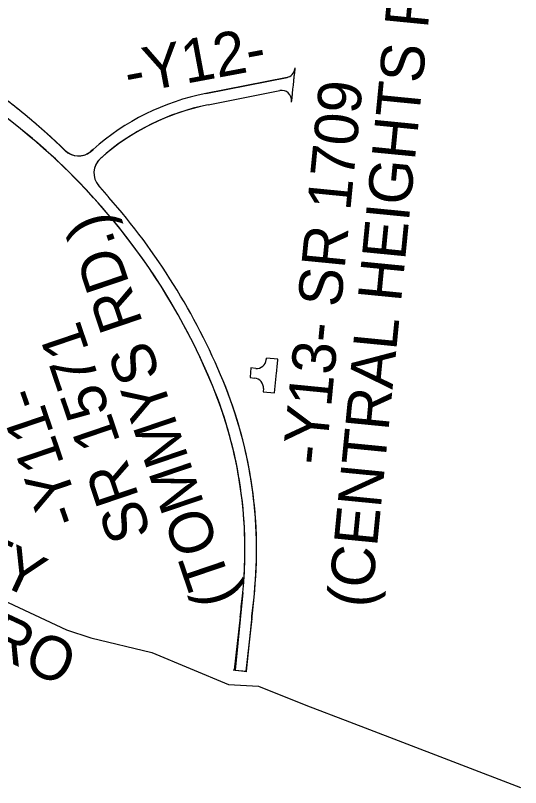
# Model space of a CAD drawing. Extents: x 2312641 to 2338852, y 590461 to 618614.
# Drawn here: x 2326941 to 2327986, y 600331 to 601928 of the extents above; entities that cross this region are included whole.
import ezdxf

# ---------------------------------------------------------------- set-up
doc = ezdxf.new("R2010")
doc.units = 0
for name, color, linetype in [('Default', 7, 'Continuous'), ('Default Symbol CELL', 7, 'Continuous'), ('Exist Property Monument CELL', 7, 'Continuous'), ('Exist Structure Minor Pipes RCP 15 Inch Text', 7, 'Continuous')]:
    doc.layers.add(name, color=color, linetype=linetype)

msp = doc.modelspace()

# ---------------------------------------------------------------- linework, layer by layer
at = {"layer": 'Default'}
msp.add_lwpolyline([(2325978.2, 601155.4), (2326135.5, 601082.1), (2326275, 601017.1), (2326389, 600964.1), (2326494.8, 600914.8), (2326611.2, 600860.6), (2326753.2, 600794.3), (2326903, 600724.6), (2327046.8, 600657.7), (2327096.8, 600640.9), (2327223, 600610.9), (2327381.8, 600544.7), (2327443.8, 600541), (2327541.5, 600502.1), (2327632, 600467.4), (2327723.5, 600432.2), (2327986, 600331.4)], dxfattribs=at)
at = {"layer": 'Default Symbol CELL'}
for p, q in [((2327334.8, 601766.9), (2327502.8, 601800.1)), ((2327339.5, 601743.3), (2327488, 601772.7)), ((2327095.9, 601646.2), (2327101.4, 601651.1)), ((2327116.8, 601632.7), (2327117.3, 601633.1)), ((2327405.8, 600684.1), (2327393.7, 600574.7)), ((2327429.7, 600681.4), (2327417.6, 600572)), ((2327391.7, 600574.9), (2327419.6, 600571.8))]:
    msp.add_line(p, q, dxfattribs=at)
for centre, radius, start, end in [((2326112, 600651.8), 1338, 22.4692, 66.2198), ((2326112, 600651.8), 1338, 22.4692, 66.2198), ((2326112, 600651.8), 1338, 22.4692, 66.2198), ((2347416.9, 599684.8), 20012, 173.87609, 174.07971), ((2327499, 601819.7), 20, 281.1907, 353.8821), ((2327491.9, 601753.1), 20, 354.0737, 101.1907), ((2327431.3, 601279.3), 497, 101.1907, 131.579), ((2327431.3, 601279.3), 473, 101.1907, 131.7849), ((2327071.3, 601677.8), 40, 225.9031, 311.579), ((2327143.2, 601602.6), 40, 131.7026, 221.5734), ((2326112, 600651.8), 1362, 22.4692, 41.3719), ((2326527.8, 600823.8), 912, 353.8058, 22.4692), ((2326527.8, 600823.8), 888, 353.8058, 22.4692), ((2306757.9, 602969.5), 20774, 353.68387, 353.80575), ((2306757.9, 602969.5), 20798, 353.68387, 353.80575)]:
    msp.add_arc(centre, radius, start, end, dxfattribs=at)
for points in [[(2326886.9, 601779.9), (2326887.7, 601779.4), (2326888.4, 601778.9), (2326889.2, 601778.4), (2326889.9, 601777.8), (2326890.6, 601777.3), (2326891.4, 601776.8), (2326892.1, 601776.2), (2326892.9, 601775.7), (2326893.6, 601775.1), (2326894.3, 601774.6), (2326895.1, 601774.1), (2326895.8, 601773.5), (2326896.6, 601773), (2326897.3, 601772.5), (2326898, 601771.9), (2326898.8, 601771.4), (2326899.5, 601770.8), (2326900.2, 601770.3), (2326901, 601769.8), (2326901.7, 601769.2), (2326902.5, 601768.7), (2326903.2, 601768.1), (2326903.9, 601767.6), (2326904.7, 601767), (2326905.4, 601766.5), (2326906.1, 601766), (2326906.9, 601765.4), (2326907.6, 601764.9), (2326908.3, 601764.3), (2326909.1, 601763.8), (2326909.8, 601763.2), (2326910.5, 601762.7), (2326911.2, 601762.1), (2326912, 601761.6), (2326912.7, 601761), (2326913.4, 601760.5), (2326914.2, 601759.9), (2326914.9, 601759.4), (2326915.6, 601758.8), (2326916.4, 601758.3), (2326917.1, 601757.7), (2326917.8, 601757.2), (2326918.5, 601756.6), (2326919.3, 601756.1), (2326920, 601755.5), (2326920.7, 601755), (2326921.4, 601754.4), (2326922.2, 601753.9), (2326922.9, 601753.3), (2326923.6, 601752.7), (2326924.3, 601752.2), (2326925.1, 601751.6), (2326925.8, 601751.1), (2326926.5, 601750.5), (2326927.2, 601750), (2326927.9, 601749.4), (2326928.7, 601748.8), (2326929.4, 601748.3), (2326930.1, 601747.7), (2326930.8, 601747.2), (2326931.6, 601746.6), (2326932.3, 601746), (2326933, 601745.5), (2326933.7, 601744.9), (2326934.4, 601744.4), (2326935.1, 601743.8), (2326935.9, 601743.2), (2326936.6, 601742.7), (2326937.3, 601742.1), (2326938, 601741.5), (2326938.7, 601741), (2326939.4, 601740.4), (2326940.2, 601739.8), (2326940.9, 601739.3)], [(2326940.9, 601739.3), (2326941.6, 601738.7), (2326942.3, 601738.1), (2326943, 601737.6), (2326943.7, 601737), (2326944.4, 601736.4), (2326945.2, 601735.8), (2326945.9, 601735.3), (2326946.6, 601734.7), (2326947.3, 601734.1), (2326948, 601733.6), (2326948.7, 601733), (2326949.4, 601732.4), (2326950.1, 601731.8), (2326950.8, 601731.3), (2326951.6, 601730.7), (2326952.3, 601730.1), (2326953, 601729.5), (2326953.7, 601729), (2326954.4, 601728.4), (2326955.1, 601727.8), (2326955.8, 601727.2), (2326956.5, 601726.7), (2326957.2, 601726.1), (2326957.9, 601725.5), (2326958.6, 601724.9), (2326959.3, 601724.3), (2326960, 601723.8), (2326960.7, 601723.2), (2326961.4, 601722.6), (2326962.1, 601722), (2326962.8, 601721.4), (2326963.5, 601720.9), (2326964.2, 601720.3), (2326965, 601719.7), (2326965.7, 601719.1), (2326966.4, 601718.5), (2326967.1, 601717.9), (2326967.8, 601717.4), (2326968.5, 601716.8), (2326969.2, 601716.2), (2326969.9, 601715.6), (2326970.5, 601715), (2326971.2, 601714.4), (2326971.9, 601713.8), (2326972.6, 601713.3), (2326973.3, 601712.7), (2326974, 601712.1), (2326974.7, 601711.5), (2326975.4, 601710.9), (2326976.1, 601710.3), (2326976.8, 601709.7), (2326977.5, 601709.1), (2326978.2, 601708.5), (2326978.9, 601707.9), (2326979.6, 601707.3), (2326980.3, 601706.8), (2326981, 601706.2), (2326981.7, 601705.6), (2326982.4, 601705), (2326983.1, 601704.4), (2326983.7, 601703.8), (2326984.4, 601703.2), (2326985.1, 601702.6), (2326985.8, 601702), (2326986.5, 601701.4), (2326987.2, 601700.8), (2326987.9, 601700.2), (2326988.6, 601699.6), (2326989.3, 601699), (2326989.9, 601698.4), (2326990.6, 601697.8), (2326991.3, 601697.2), (2326992, 601696.6), (2326992.7, 601696)], [(2326992.7, 601696), (2326993.4, 601695.4), (2326994.1, 601694.8), (2326994.7, 601694.2), (2326995.4, 601693.6), (2326996.1, 601693), (2326996.8, 601692.4), (2326997.5, 601691.8), (2326998.2, 601691.2), (2326998.8, 601690.6), (2326999.5, 601690), (2327000.2, 601689.4), (2327000.9, 601688.8), (2327001.6, 601688.1), (2327002.2, 601687.5), (2327002.9, 601686.9), (2327003.6, 601686.3), (2327004.3, 601685.7), (2327005, 601685.1), (2327005.6, 601684.5), (2327006.3, 601683.9), (2327007, 601683.3), (2327007.7, 601682.7), (2327008.3, 601682), (2327009, 601681.4), (2327009.7, 601680.8), (2327010.4, 601680.2), (2327011, 601679.6), (2327011.7, 601679), (2327012.4, 601678.4), (2327013.1, 601677.8), (2327013.7, 601677.1), (2327014.4, 601676.5), (2327015.1, 601675.9), (2327015.7, 601675.3), (2327016.4, 601674.7), (2327017.1, 601674.1), (2327017.8, 601673.4), (2327018.4, 601672.8), (2327019.1, 601672.2), (2327019.8, 601671.6), (2327020.4, 601671), (2327021.1, 601670.3), (2327021.8, 601669.7), (2327022.4, 601669.1), (2327023.1, 601668.5), (2327023.8, 601667.9), (2327024.4, 601667.2), (2327025.1, 601666.6), (2327025.8, 601666), (2327026.4, 601665.4), (2327027.1, 601664.7), (2327027.8, 601664.1), (2327028.4, 601663.5), (2327029.1, 601662.9), (2327029.7, 601662.2), (2327030.4, 601661.6), (2327031.1, 601661), (2327031.7, 601660.4), (2327032.4, 601659.7), (2327033, 601659.1), (2327033.7, 601658.5), (2327034.4, 601657.9), (2327035, 601657.2), (2327035.7, 601656.6), (2327036.3, 601656), (2327037, 601655.3), (2327037.7, 601654.7), (2327038.3, 601654.1), (2327039, 601653.4), (2327039.6, 601652.8), (2327040.3, 601652.2), (2327040.9, 601651.5), (2327041.6, 601650.9), (2327042.2, 601650.3)], [(2327042.2, 601650.3), (2327042.9, 601649.6), (2327043.5, 601649.1)], [(2327113, 601576.3), (2327113.3, 601576), (2327113.9, 601575.3), (2327114.5, 601574.6), (2327115.1, 601573.9), (2327115.7, 601573.3), (2327116.3, 601572.6), (2327116.9, 601571.9), (2327117.5, 601571.2), (2327118.1, 601570.5), (2327118.7, 601569.8), (2327119.3, 601569.2), (2327119.9, 601568.5), (2327120.5, 601567.8), (2327121.1, 601567.1), (2327121.7, 601566.4), (2327122.3, 601565.7), (2327122.9, 601565), (2327123.5, 601564.4), (2327124.1, 601563.7), (2327124.7, 601563), (2327125.3, 601562.3), (2327125.9, 601561.6), (2327126.5, 601560.9), (2327127.1, 601560.2), (2327127.7, 601559.5), (2327128.3, 601558.8), (2327128.9, 601558.2), (2327129.5, 601557.5), (2327130, 601556.8), (2327130.6, 601556.1), (2327131.2, 601555.4), (2327131.8, 601554.7), (2327132.4, 601554), (2327133, 601553.3), (2327134.1, 601552)]]:
    msp.add_spline(points, degree=3, dxfattribs=at)
at = {"layer": 'Exist Property Monument CELL'}
for p, q in [((2327502.8, 601800.1), (2327334.8, 601766.9)), ((2327339.5, 601743.3), (2327488, 601772.7)), ((2326940.9, 601739.3), (2326940.9, 601739.3)), ((2326992.7, 601696), (2326992.7, 601696)), ((2327042.2, 601650.3), (2327042.2, 601650.3)), ((2327095.9, 601646.2), (2327095.8, 601646.2)), ((2327116.1, 601632), (2327116.1, 601632)), ((2327116.8, 601632.7), (2327117.3, 601633.1)), ((2327116.8, 601632.7), (2327116.8, 601632.7)), ((2327113, 601576.3), (2327113, 601576.3)), ((2327484.1, 601217.3), (2327460.2, 601219.7)), ((2327428.1, 601199.2), (2327426.2, 601179.9)), ((2327438, 601198.3), (2327428.1, 601199.2)), ((2327426.2, 601179.9), (2327426.2, 601179.3)), ((2327477.1, 601147.7), (2327481.3, 601189.2)), ((2327426.2, 601179.3), (2327435.8, 601178.4)), ((2327453.8, 601156.5), (2327453.2, 601150.1)), ((2327411.4, 600734.8), (2327395.2, 600574.4)), ((2327419.1, 600572), (2327435.2, 600732.4)), ((2327395.2, 600574.4), (2327419.1, 600572))]:
    msp.add_line(p, q, dxfattribs=at)
for points in [[(2327101.4, 601651.1), (2327097.8, 601647.9), (2327095.9, 601646.2)], [(2327426.2, 601179.9), (2327426.2, 601179.9)], [(2327453.2, 601150.1), (2327453.6, 601150), (2327476.9, 601147.7), (2327477.1, 601147.7)]]:
    msp.add_lwpolyline(points, dxfattribs=at)
for centre, radius, start, end in [((2327499, 601819.7), 20, 281.1907, 353.8821), ((2347416.9, 599684.8), 20012, 173.88209, 174.07372), ((2327491.9, 601753.1), 20, 354.0737, 101.1907), ((2327431.3, 601279.3), 497, 101.1907, 131.579), ((2327431.3, 601279.3), 473, 101.1907, 131.579), ((2326112, 600651.8), 1338, 22.4692, 54.1092), ((2327071.3, 601677.8), 40, 225.9031, 307.8068), ((2327143.2, 601602.6), 40, 132.6764, 220.9895), ((2327431.3, 601279.3), 473, 131.6658, 131.7849), ((2326112, 600651.8), 1362, 22.4692, 41.3719), ((2327439.9, 601218.2), 20, 264.5126, 354.3769), ((2316524.7, 602292.9), 10988, 354.37687, 354.39508), ((2316524.7, 602292.9), 11012, 354.24813, 354.39508), ((2326527.8, 600823.8), 912, 354.2481, 22.4692), ((2327433.9, 601158.5), 20, 354.2481, 84.5126), ((2326527.8, 600823.8), 888, 354.2481, 22.4692)]:
    msp.add_arc(centre, radius, start, end, dxfattribs=at)
for points in [[(2326940.9, 601739.3), (2326940.2, 601739.8), (2326939.4, 601740.4), (2326938.7, 601741), (2326938, 601741.5), (2326937.3, 601742.1), (2326936.6, 601742.7), (2326935.9, 601743.2), (2326935.1, 601743.8), (2326934.4, 601744.4), (2326933.7, 601744.9), (2326933, 601745.5), (2326932.3, 601746), (2326931.6, 601746.6), (2326930.8, 601747.2), (2326930.1, 601747.7), (2326929.4, 601748.3), (2326928.7, 601748.8), (2326927.9, 601749.4), (2326927.2, 601750), (2326926.5, 601750.5), (2326925.8, 601751.1), (2326925.1, 601751.6), (2326924.3, 601752.2), (2326923.6, 601752.7), (2326923.1, 601753.1)], [(2326958.4, 601725.1), (2326957.9, 601725.5), (2326957.2, 601726.1), (2326956.5, 601726.7), (2326955.8, 601727.2), (2326955.1, 601727.8), (2326954.4, 601728.4), (2326953.7, 601729), (2326953, 601729.5), (2326952.3, 601730.1), (2326951.6, 601730.7), (2326950.8, 601731.3), (2326950.1, 601731.8), (2326949.4, 601732.4), (2326948.7, 601733), (2326948, 601733.6), (2326947.3, 601734.1), (2326946.6, 601734.7), (2326945.9, 601735.3), (2326945.2, 601735.8), (2326944.4, 601736.4), (2326943.7, 601737), (2326943, 601737.6), (2326942.3, 601738.1), (2326941.6, 601738.7), (2326940.9, 601739.3)], [(2326975.7, 601710.7), (2326975.4, 601710.9), (2326974.7, 601711.5), (2326974, 601712.1), (2326973.3, 601712.7), (2326972.6, 601713.3), (2326971.9, 601713.8), (2326971.2, 601714.4), (2326970.5, 601715), (2326969.9, 601715.6), (2326969.2, 601716.2), (2326968.5, 601716.8), (2326967.8, 601717.4), (2326967.1, 601717.9), (2326966.4, 601718.5), (2326965.7, 601719.1), (2326965, 601719.7), (2326964.2, 601720.3), (2326963.5, 601720.9), (2326962.8, 601721.4), (2326962.1, 601722), (2326961.4, 601722.6), (2326960.7, 601723.2), (2326960, 601723.8), (2326959.3, 601724.3), (2326958.6, 601724.9), (2326958.4, 601725.1)], [(2326992.7, 601696), (2326992, 601696.6), (2326991.3, 601697.2), (2326990.6, 601697.8), (2326989.9, 601698.4), (2326989.3, 601699), (2326988.6, 601699.6), (2326987.9, 601700.2), (2326987.2, 601700.8), (2326986.5, 601701.4), (2326985.8, 601702), (2326985.1, 601702.6), (2326984.4, 601703.2), (2326983.7, 601703.8), (2326983.1, 601704.4), (2326982.4, 601705), (2326981.7, 601705.6), (2326981, 601706.2), (2326980.3, 601706.8), (2326979.6, 601707.3), (2326978.9, 601707.9), (2326978.2, 601708.5), (2326977.5, 601709.1), (2326976.8, 601709.7), (2326976.1, 601710.3), (2326975.7, 601710.7)], [(2327009.5, 601681), (2327009, 601681.4), (2327008.3, 601682), (2327007.7, 601682.7), (2327007, 601683.3), (2327006.3, 601683.9), (2327005.6, 601684.5), (2327005, 601685.1), (2327004.3, 601685.7), (2327003.6, 601686.3), (2327002.9, 601686.9), (2327002.2, 601687.5), (2327001.6, 601688.1), (2327000.9, 601688.8), (2327000.2, 601689.4), (2326999.5, 601690), (2326998.8, 601690.6), (2326998.2, 601691.2), (2326997.5, 601691.8), (2326996.8, 601692.4), (2326996.1, 601693), (2326995.4, 601693.6), (2326994.7, 601694.2), (2326994.1, 601694.8), (2326993.4, 601695.4), (2326992.7, 601696)], [(2327026, 601665.8), (2327025.8, 601666), (2327025.1, 601666.6), (2327024.4, 601667.2), (2327023.8, 601667.9), (2327023.1, 601668.5), (2327022.4, 601669.1), (2327021.8, 601669.7), (2327021.1, 601670.3), (2327020.4, 601671), (2327019.8, 601671.6), (2327019.1, 601672.2), (2327018.4, 601672.8), (2327017.8, 601673.4), (2327017.1, 601674.1), (2327016.4, 601674.7), (2327015.7, 601675.3), (2327015.1, 601675.9), (2327014.4, 601676.5), (2327013.7, 601677.1), (2327013.1, 601677.8), (2327012.4, 601678.4), (2327011.7, 601679), (2327011, 601679.6), (2327010.4, 601680.2), (2327009.7, 601680.8), (2327009.5, 601681)], [(2327042.2, 601650.3), (2327041.6, 601650.9), (2327040.9, 601651.5), (2327040.3, 601652.2), (2327039.6, 601652.8), (2327039, 601653.4), (2327038.3, 601654.1), (2327037.7, 601654.7), (2327037, 601655.3), (2327036.3, 601656), (2327035.7, 601656.6), (2327035, 601657.2), (2327034.4, 601657.9), (2327033.7, 601658.5), (2327033, 601659.1), (2327032.4, 601659.7), (2327031.7, 601660.4), (2327031.1, 601661), (2327030.4, 601661.6), (2327029.7, 601662.2), (2327029.1, 601662.9), (2327028.4, 601663.5), (2327027.8, 601664.1), (2327027.1, 601664.7), (2327026.4, 601665.4), (2327026, 601665.8)], [(2327043.5, 601649.1), (2327042.9, 601649.6), (2327042.2, 601650.3)], [(2327134.1, 601552), (2327133, 601553.3), (2327132.4, 601554), (2327131.8, 601554.7), (2327131.2, 601555.4), (2327130.6, 601556.1), (2327130, 601556.8), (2327129.5, 601557.5), (2327128.9, 601558.2), (2327128.3, 601558.8), (2327127.7, 601559.5), (2327127.1, 601560.2), (2327126.5, 601560.9), (2327125.9, 601561.6), (2327125.3, 601562.3), (2327124.7, 601563), (2327124.1, 601563.7), (2327123.6, 601564.2)]]:
    msp.add_spline(points, degree=3, dxfattribs=at)
msp.add_open_spline([(2327123.6, 601564.2), (2327123.6, 601564.3), (2327123.6, 601564.3), (2327123.5, 601564.4), (2327123.3, 601564.6), (2327123.1, 601564.8), (2327122.9, 601565), (2327122.7, 601565.3), (2327122.5, 601565.5), (2327122.3, 601565.7), (2327122.1, 601566), (2327121.9, 601566.2), (2327121.7, 601566.4), (2327121.5, 601566.6), (2327121.3, 601566.9), (2327121.1, 601567.1), (2327120.9, 601567.3), (2327120.7, 601567.6), (2327120.5, 601567.8), (2327120.3, 601568), (2327120.1, 601568.2), (2327119.9, 601568.5), (2327119.7, 601568.7), (2327119.5, 601568.9), (2327119.3, 601569.2), (2327119.1, 601569.4), (2327118.9, 601569.6), (2327118.7, 601569.8), (2327118.5, 601570.1), (2327118.3, 601570.3), (2327118.1, 601570.5), (2327117.9, 601570.7), (2327117.7, 601571), (2327117.5, 601571.2), (2327117.3, 601571.4), (2327117.1, 601571.7), (2327116.9, 601571.9), (2327116.7, 601572.1), (2327116.5, 601572.3), (2327116.3, 601572.6), (2327116.1, 601572.8), (2327115.9, 601573), (2327115.7, 601573.3), (2327115.5, 601573.5), (2327115.3, 601573.7), (2327115.1, 601573.9), (2327114.9, 601574.2), (2327114.7, 601574.4), (2327114.5, 601574.6), (2327114.3, 601574.8), (2327114.1, 601575.1), (2327113.9, 601575.3), (2327113.7, 601575.5), (2327113.5, 601575.8), (2327113.3, 601576), (2327113.2, 601576.1), (2327113.1, 601576.2), (2327113, 601576.3)], degree=3, dxfattribs=at)

# ---------------------------------------------------------------- texts
at = {"layer": 'Default'}
for s, p in [('WAYNE COUNTY', (2326083.8, 601135.4)), ('CITY OF GOLDSBORO', (2325874.1, 601081.1))]:
    msp.add_text(s, height=90, rotation=335.0248, dxfattribs=at).set_placement(p)
at = {"layer": 'Exist Structure Minor Pipes RCP 15 Inch Text'}
for s, rotation, p in [('(CENTRAL HEIGHTS RD.)', 84.4043, (2327676.6, 600701.6)), ('-Y12-', 10.5824, (2327174.7, 601764.8)), ('-Y13- SR 1709', 84.4043, (2327582.1, 600996.7)), ('(TOMMYS RD.)', 108.7228, (2327398.5, 600721.9)), ('SR 1571', 108.7228, (2327223.1, 600856.6)), ('-Y11-', 108.6888, (2327081.2, 600887.5))]:
    msp.add_text(s, height=90, rotation=rotation, dxfattribs=at).set_placement(p)

doc.saveas('drawing.dxf')
